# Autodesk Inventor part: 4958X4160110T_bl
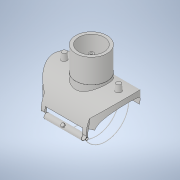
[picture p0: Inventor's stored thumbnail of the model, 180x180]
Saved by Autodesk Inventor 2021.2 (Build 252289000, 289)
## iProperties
Created: 2020-06
Part Number: 4958X4160110T_bl
Material: Generic
Description: Plasson Branch Saddle 160x110
Document SubType Name: Modeling
Designer: KIM
Density: 1 g/cm^3
Appearance: Default
Author: KIM
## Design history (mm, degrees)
derived "4958X4.ipt"
feature "Solid1::4958X4.ipt" dims "ScaleForDerivedMember" = 10
tag "TaggingFeature1"
body "Solid1"
other parameters: "d0" = 263 [user parameter], "d3" = 195.4 [user parameter], "d7" = 89 [user parameter], "d9" = 84 [user parameter], "d10" = 0.5 [user parameter], "d11" = 1 [user parameter], "d12" = 27.5 [user parameter], "d13" = 16 [user parameter], "d14" = 8 [user parameter], "d16" = 10 deg [user parameter], "d17" = 10 deg [user parameter], "d19" = 0 [user parameter], "d23" = 0 [user parameter], "d26" = 0 [user parameter], "d27" = 157.8 [user parameter], "d28" = 0 [user parameter], "d29" = 131.5 [user parameter], "d30" = 0 [user parameter], "d31" = 1 [user parameter], "d32" = 1 [user parameter], "d33" = 19.2 [user parameter], "d34" = 9.6 [user parameter], "d35" = 45 deg [user parameter], "d36" = 131.5 [user parameter], "d37" = 0 [user parameter], "d38" = 5 [user parameter], "d39" = 85 deg [user parameter], "d40" = 27.5 [user parameter], "d41" = 16 [user parameter], "d42" = 95.63636 [user parameter], "d49" = 3 [user parameter], "d50" = 6 [user parameter], "d51" = 5 [user parameter], "d54" = 0 [user parameter], "d57" = 35 deg [user parameter], "d60" = 16.4375 [user parameter], "d61" = 1 [user parameter], "d62" = 90 deg [user parameter], "d63" = 2 [user parameter], "d64" = 0 [user parameter], "d65" = 0 [user parameter], "d68" = 32.875 [user parameter], "d70" = 0.57711 [user parameter], "d71" = 10 deg [user parameter], "d73" = 6.195 [user parameter], "B" = 219 [user parameter], "L" = 263 [user parameter], "LS" = 84 [user parameter], "Dt" = 16 [user parameter], "di" = 89 [user parameter], "d72" = 17.7 [user parameter]
